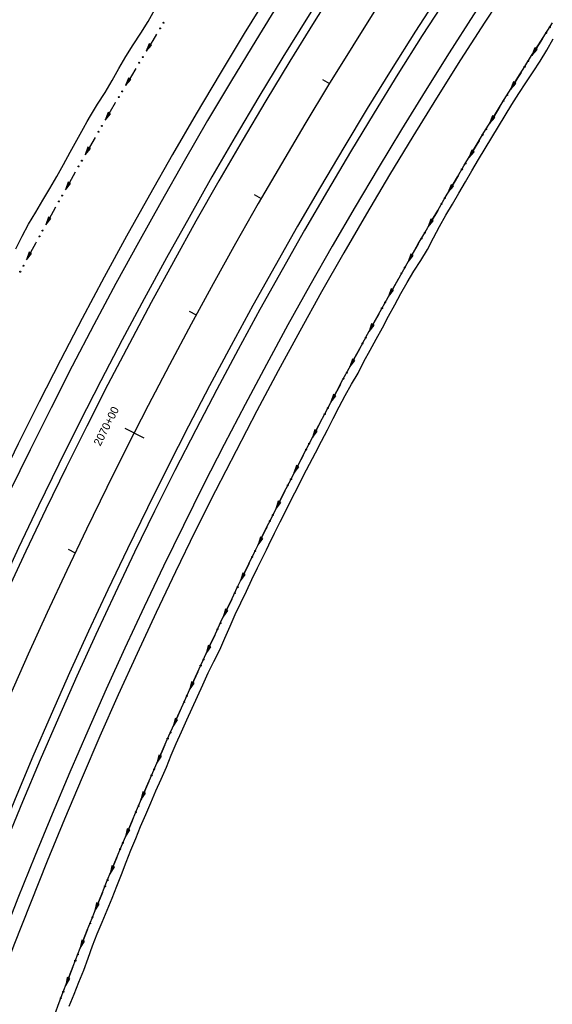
# Model space of a CAD drawing. Extents: x 1611108 to 1749517, y 619561 to 797725.
# Drawn here: x 1713935 to 1714335, y 763528 to 764266 of the extents above; entities that cross this region are included whole.
import ezdxf

# ---------------------------------------------------------------- set-up
doc = ezdxf.new("R2010")
doc.units = 0
for name, color, linetype in [('R_Ditch', 7, 'Continuous'), ('R_Horz Alg', 7, 'Continuous'), ('R_Horz Alg Stationing', 7, 'Continuous'), ('R_Proposed Const Limits', 7, 'Continuous'), ('R_Proposed Road', 7, 'Continuous')]:
    doc.layers.add(name, color=color, linetype=linetype)

msp = doc.modelspace()

# ---------------------------------------------------------------- linework, layer by layer
at = {"layer": 'R_Ditch'}
for p, q in [((1714032.43, 764248.1), (1714030.22, 764242.42)), ((1714032.43, 764248.1), (1714030.22, 764242.42)), ((1714030.22, 764242.42), (1714034.24, 764247)), ((1714030.22, 764242.42), (1714034.24, 764247)), ((1714034.24, 764247), (1714032.43, 764248.1)), ((1714034.24, 764247), (1714032.43, 764248.1)), ((1714321.47, 764244.96), (1714319.15, 764239.33)), ((1714319.15, 764239.33), (1714323.25, 764243.83)), ((1714323.25, 764243.83), (1714321.47, 764244.96)), ((1714016.92, 764222.37), (1714014.76, 764216.67)), ((1714016.92, 764222.37), (1714014.76, 764216.67)), ((1714018.74, 764221.28), (1714016.92, 764222.37)), ((1714018.74, 764221.28), (1714016.92, 764222.37)), ((1714014.76, 764216.67), (1714018.74, 764221.28)), ((1714014.76, 764216.67), (1714018.74, 764221.28)), ((1714305.5, 764219.51), (1714303.23, 764213.86)), ((1714303.23, 764213.86), (1714307.3, 764218.39)), ((1714307.3, 764218.39), (1714305.5, 764219.51)), ((1714001.62, 764196.51), (1713999.51, 764190.79)), ((1714001.62, 764196.51), (1713999.51, 764190.79)), ((1713999.51, 764190.79), (1714003.45, 764195.44)), ((1713999.51, 764190.79), (1714003.45, 764195.44)), ((1714003.45, 764195.44), (1714001.62, 764196.51)), ((1714003.45, 764195.44), (1714001.62, 764196.51)), ((1714289.73, 764193.94), (1714287.5, 764188.27)), ((1714287.5, 764188.27), (1714291.53, 764192.84)), ((1714291.53, 764192.84), (1714289.73, 764193.94)), ((1713986.53, 764170.52), (1713984.47, 764164.79)), ((1713986.53, 764170.52), (1713984.47, 764164.79)), ((1713988.37, 764169.47), (1713986.53, 764170.52)), ((1713988.37, 764169.47), (1713986.53, 764170.52)), ((1713984.47, 764164.79), (1713988.37, 764169.47)), ((1713984.47, 764164.79), (1713988.37, 764169.47)), ((1714274.15, 764168.25), (1714271.96, 764162.56)), ((1714271.96, 764162.56), (1714275.96, 764167.16)), ((1714275.96, 764167.16), (1714274.15, 764168.25)), ((1713971.66, 764144.42), (1713969.64, 764138.67)), ((1713971.66, 764144.42), (1713969.64, 764138.67)), ((1713969.64, 764138.67), (1713973.5, 764143.38)), ((1713969.64, 764138.67), (1713973.5, 764143.38)), ((1713973.5, 764143.38), (1713971.66, 764144.42)), ((1713973.5, 764143.38), (1713971.66, 764144.42)), ((1714258.75, 764142.44), (1714256.62, 764136.74)), ((1714256.62, 764136.74), (1714260.58, 764141.37)), ((1714260.58, 764141.37), (1714258.75, 764142.44)), ((1713956.99, 764118.19), (1713955.02, 764112.43)), ((1713956.99, 764118.19), (1713955.02, 764112.43)), ((1713958.84, 764117.17), (1713956.99, 764118.19)), ((1713958.84, 764117.17), (1713956.99, 764118.19)), ((1713955.02, 764112.43), (1713958.84, 764117.17)), ((1713955.02, 764112.43), (1713958.84, 764117.17)), ((1714243.56, 764116.52), (1714241.47, 764110.8)), ((1714241.47, 764110.8), (1714245.4, 764115.46)), ((1714245.4, 764115.46), (1714243.56, 764116.52)), ((1713942.54, 764091.85), (1713940.61, 764086.07)), ((1713942.54, 764091.85), (1713940.61, 764086.07)), ((1713940.61, 764086.07), (1713944.4, 764090.85)), ((1713940.61, 764086.07), (1713944.4, 764090.85)), ((1713944.4, 764090.85), (1713942.54, 764091.85)), ((1713944.4, 764090.85), (1713942.54, 764091.85)), ((1714228.57, 764090.48), (1714226.52, 764084.74)), ((1714226.52, 764084.74), (1714230.41, 764089.44)), ((1714230.41, 764089.44), (1714228.57, 764090.48)), ((1714213.77, 764064.33), (1714211.77, 764058.58)), ((1714211.77, 764058.58), (1714215.62, 764063.3)), ((1714215.62, 764063.3), (1714213.77, 764064.33)), ((1714199.17, 764038.07), (1714197.21, 764032.31)), ((1714197.21, 764032.31), (1714201.03, 764037.05)), ((1714201.03, 764037.05), (1714199.17, 764038.07)), ((1714184.77, 764011.7), (1714182.85, 764005.92)), ((1714182.85, 764005.92), (1714186.63, 764010.7)), ((1714186.63, 764010.7), (1714184.77, 764011.7)), ((1714170.57, 763985.23), (1714168.69, 763979.43)), ((1714168.69, 763979.43), (1714172.44, 763984.23)), ((1714172.44, 763984.23), (1714170.57, 763985.23)), ((1714156.57, 763958.64), (1714154.73, 763952.84)), ((1714154.73, 763952.84), (1714158.44, 763957.67)), ((1714158.44, 763957.67), (1714156.57, 763958.64)), ((1714142.76, 763931.96), (1714140.97, 763926.13)), ((1714140.97, 763926.13), (1714144.65, 763930.99)), ((1714144.65, 763930.99), (1714142.76, 763931.96)), ((1714129.16, 763905.17), (1714127.41, 763899.33)), ((1714127.41, 763899.33), (1714131.05, 763904.21)), ((1714131.05, 763904.21), (1714129.16, 763905.17)), ((1714115.76, 763878.27), (1714114.06, 763872.42)), ((1714114.06, 763872.42), (1714117.66, 763877.34)), ((1714117.66, 763877.34), (1714115.76, 763878.27)), ((1714102.57, 763851.28), (1714100.91, 763845.41)), ((1714100.91, 763845.41), (1714104.47, 763850.36)), ((1714104.47, 763850.36), (1714102.57, 763851.28)), ((1714089.58, 763824.19), (1714087.97, 763818.31)), ((1714087.97, 763818.31), (1714091.49, 763823.28)), ((1714091.49, 763823.28), (1714089.58, 763824.19)), ((1714076.79, 763797), (1714075.22, 763791.11)), ((1714075.22, 763791.11), (1714078.71, 763796.1)), ((1714078.71, 763796.1), (1714076.79, 763797)), ((1714064.21, 763769.71), (1714062.69, 763763.81)), ((1714062.69, 763763.81), (1714066.14, 763768.83)), ((1714066.14, 763768.83), (1714064.21, 763769.71)), ((1714051.84, 763742.33), (1714050.36, 763736.42)), ((1714053.77, 763741.47), (1714051.84, 763742.33)), ((1714050.36, 763736.42), (1714053.77, 763741.47)), ((1714039.67, 763714.86), (1714038.23, 763708.94)), ((1714038.23, 763708.94), (1714041.61, 763714.01)), ((1714041.61, 763714.01), (1714039.67, 763714.86)), ((1714027.71, 763687.3), (1714026.32, 763681.36)), ((1714026.32, 763681.36), (1714029.66, 763686.46)), ((1714029.66, 763686.46), (1714027.71, 763687.3)), ((1714015.96, 763659.64), (1714014.61, 763653.7)), ((1714014.61, 763653.7), (1714017.91, 763658.82)), ((1714017.91, 763658.82), (1714015.96, 763659.64)), ((1714004.42, 763631.9), (1714003.11, 763625.95)), ((1714003.11, 763625.95), (1714006.38, 763631.1)), ((1714006.38, 763631.1), (1714004.42, 763631.9)), ((1713993.08, 763604.08), (1713991.83, 763598.11)), ((1713991.83, 763598.11), (1713995.04, 763603.29)), ((1713995.04, 763603.29), (1713993.08, 763604.08)), ((1713981.96, 763576.16), (1713980.75, 763570.19)), ((1713980.75, 763570.19), (1713983.93, 763575.39)), ((1713983.93, 763575.39), (1713981.96, 763576.16)), ((1713971.05, 763548.17), (1713969.89, 763542.19)), ((1713969.89, 763542.19), (1713973.02, 763547.41)), ((1713973.02, 763547.41), (1713971.05, 763548.17))]:
    msp.add_line(p, q, dxfattribs=at)
for points in [[(1713961.65, 763520.54), (1713965.07, 763529.59), (1713968.53, 763538.64), (1713972, 763547.68), (1713975.49, 763556.71), (1713979, 763565.74), (1713982.54, 763574.75), (1713986.1, 763583.76), (1713989.68, 763592.75), (1713993.28, 763601.74), (1713996.91, 763610.72), (1714000.55, 763619.69), (1714004.22, 763628.65), (1714007.91, 763637.6), (1714011.62, 763646.55), (1714015.36, 763655.48), (1714019.11, 763664.41), (1714022.89, 763673.32), (1714026.69, 763682.23), (1714030.51, 763691.13), (1714034.35, 763700.02), (1714038.22, 763708.89), (1714042.1, 763717.76), (1714046.01, 763726.62), (1714049.94, 763735.47), (1714053.88, 763744.32), (1714057.86, 763753.15), (1714061.85, 763761.97), (1714065.86, 763770.78), (1714069.9, 763779.58), (1714073.96, 763788.37), (1714078.03, 763797.16), (1714082.13, 763805.93), (1714086.26, 763814.69), (1714090.4, 763823.45), (1714094.56, 763832.19), (1714098.75, 763840.92), (1714102.95, 763849.64), (1714107.18, 763858.36), (1714111.43, 763867.06), (1714113.87, 763872.03), (1714115.7, 763875.75), (1714119.99, 763884.43), (1714124.3, 763893.1), (1714128.64, 763901.77), (1714132.99, 763910.42), (1714137.37, 763919.06), (1714141.76, 763927.69), (1714146.18, 763936.3), (1714150.62, 763944.91), (1714155.08, 763953.51), (1714159.56, 763962.1), (1714160.41, 763963.72), (1714164.06, 763970.67), (1714168.58, 763979.24), (1714173.13, 763987.79), (1714177.69, 763996.34), (1714182.28, 764004.87), (1714186.89, 764013.39), (1714191.51, 764021.9), (1714196.16, 764030.4), (1714200.83, 764038.89), (1714205.52, 764047.37), (1714210.23, 764055.83), (1714214.96, 764064.29), (1714219.71, 764072.73), (1714224.48, 764081.16), (1714229.28, 764089.58), (1714234.09, 764097.99), (1714238.92, 764106.39), (1714243.78, 764114.77), (1714248.65, 764123.15), (1714253.55, 764131.51), (1714258.46, 764139.86), (1714263.4, 764148.2), (1714268.35, 764156.53), (1714273.33, 764164.84), (1714278.33, 764173.15), (1714283.35, 764181.44), (1714288.39, 764189.72), (1714293.44, 764197.99), (1714298.52, 764206.24), (1714303.62, 764214.49), (1714308.74, 764222.72), (1714313.88, 764230.94), (1714319.04, 764239.14), (1714324.22, 764247.34), (1714329.42, 764255.52), (1714334.64, 764263.69)], [(1714038.02, 764255.24), (1714035.18, 764250.58), (1714030.22, 764242.42)], [(1714038.02, 764255.24), (1714035.18, 764250.58), (1714030.22, 764242.42)], [(1714038.04, 764255.27), (1714038.02, 764255.24)], [(1714038.04, 764255.27), (1714038.02, 764255.24)], [(1714327.18, 764252), (1714324.22, 764247.34), (1714319.15, 764239.33)], [(1714327.2, 764252.03), (1714327.18, 764252)], [(1714022.46, 764229.55), (1714019.14, 764224.02), (1714014.76, 764216.67)], [(1714022.46, 764229.55), (1714019.14, 764224.02), (1714014.76, 764216.67)], [(1714022.48, 764229.58), (1714022.46, 764229.55)], [(1714022.48, 764229.58), (1714022.46, 764229.55)], [(1714311.16, 764226.59), (1714308.74, 764222.72), (1714303.62, 764214.49), (1714303.23, 764213.86)], [(1714311.18, 764226.62), (1714311.16, 764226.59)], [(1714007.1, 764203.73), (1714003.33, 764197.33), (1713999.51, 764190.79)], [(1714007.1, 764203.73), (1714003.33, 764197.33), (1713999.51, 764190.79)], [(1714007.12, 764203.76), (1714007.1, 764203.73)], [(1714007.12, 764203.76), (1714007.1, 764203.73)], [(1714295.33, 764201.06), (1714293.44, 764197.99), (1714288.39, 764189.72), (1714287.5, 764188.27)], [(1714295.35, 764201.09), (1714295.33, 764201.06)], [(1713991.95, 764177.79), (1713987.74, 764170.5), (1713984.47, 764164.79)], [(1713991.95, 764177.79), (1713987.74, 764170.5), (1713984.47, 764164.79)], [(1713991.97, 764177.82), (1713991.95, 764177.79)], [(1713991.97, 764177.82), (1713991.95, 764177.79)], [(1714279.7, 764175.41), (1714278.33, 764173.15), (1714273.33, 764164.84), (1714271.96, 764162.56)], [(1714279.72, 764175.44), (1714279.7, 764175.41)], [(1713977.01, 764151.73), (1713972.38, 764143.54), (1713969.64, 764138.67)], [(1713977.01, 764151.73), (1713972.38, 764143.54), (1713969.64, 764138.67)], [(1713977.03, 764151.76), (1713977.01, 764151.73)], [(1713977.03, 764151.76), (1713977.01, 764151.73)], [(1714264.26, 764149.65), (1714263.4, 764148.2), (1714258.46, 764139.86), (1714256.62, 764136.74)], [(1714264.28, 764149.68), (1714264.26, 764149.65)], [(1713962.29, 764125.55), (1713962.26, 764125.5), (1713957.24, 764116.46), (1713955.02, 764112.43)], [(1713962.29, 764125.55), (1713962.26, 764125.5), (1713957.24, 764116.46), (1713955.02, 764112.43)], [(1713962.31, 764125.58), (1713962.29, 764125.55)], [(1713962.31, 764125.58), (1713962.29, 764125.55)], [(1714249.01, 764123.77), (1714248.65, 764123.15), (1714243.78, 764114.77), (1714241.47, 764110.8)], [(1714249.03, 764123.8), (1714249.01, 764123.77)], [(1713947.78, 764099.25), (1713947.27, 764098.33), (1713942.33, 764089.24), (1713940.61, 764086.07)], [(1713947.78, 764099.25), (1713947.27, 764098.33), (1713942.33, 764089.24), (1713940.61, 764086.07)], [(1713947.8, 764099.28), (1713947.78, 764099.25)], [(1713947.8, 764099.28), (1713947.78, 764099.25)], [(1714233.96, 764097.77), (1714229.28, 764089.58), (1714226.52, 764084.74)], [(1714233.98, 764097.8), (1714233.96, 764097.77)], [(1714219.11, 764071.66), (1714214.96, 764064.29), (1714211.77, 764058.58)], [(1714219.13, 764071.69), (1714219.11, 764071.66)], [(1714204.45, 764045.44), (1714200.83, 764038.89), (1714197.21, 764032.31)], [(1714204.47, 764045.47), (1714204.45, 764045.44)], [(1714190, 764019.11), (1714186.89, 764013.39), (1714182.85, 764005.92)], [(1714190.01, 764019.14), (1714190, 764019.11)], [(1714175.74, 763992.67), (1714173.13, 763987.79), (1714168.69, 763979.43)], [(1714175.75, 763992.71), (1714175.74, 763992.67)], [(1714161.68, 763966.13), (1714160.41, 763963.72), (1714159.56, 763962.1), (1714155.08, 763953.51), (1714154.73, 763952.83)], [(1714161.69, 763966.16), (1714161.68, 763966.13)], [(1714147.82, 763939.48), (1714146.18, 763936.3), (1714141.76, 763927.69), (1714140.97, 763926.13)], [(1714147.84, 763939.51), (1714147.82, 763939.48)], [(1714134.16, 763912.73), (1714132.99, 763910.42), (1714128.64, 763901.77), (1714127.42, 763899.33)], [(1714134.18, 763912.76), (1714134.16, 763912.73)], [(1714120.7, 763885.87), (1714119.99, 763884.43), (1714115.7, 763875.75), (1714114.06, 763872.42)], [(1714120.72, 763885.9), (1714120.7, 763885.87)], [(1714107.45, 763858.91), (1714107.18, 763858.36), (1714102.95, 763849.64), (1714100.91, 763845.41)], [(1714107.47, 763858.95), (1714107.45, 763858.91)], [(1714094.4, 763831.86), (1714090.4, 763823.45), (1714087.97, 763818.31)], [(1714094.42, 763831.89), (1714094.4, 763831.86)], [(1714081.56, 763804.7), (1714078.03, 763797.16), (1714075.22, 763791.11)], [(1714081.58, 763804.74), (1714081.56, 763804.7)], [(1714068.92, 763777.45), (1714065.86, 763770.78), (1714062.69, 763763.81)], [(1714068.94, 763777.49), (1714068.92, 763777.45)], [(1714056.49, 763750.11), (1714053.88, 763744.32), (1714050.36, 763736.42)], [(1714056.51, 763750.14), (1714056.49, 763750.11)], [(1714044.26, 763722.67), (1714042.1, 763717.76), (1714038.23, 763708.94)], [(1714044.28, 763722.71), (1714044.27, 763722.67)], [(1714032.25, 763695.14), (1714030.51, 763691.13), (1714026.69, 763682.23), (1714026.32, 763681.36)], [(1714032.26, 763695.18), (1714032.25, 763695.14)], [(1714020.44, 763667.53), (1714019.11, 763664.41), (1714015.36, 763655.48), (1714014.61, 763653.7)], [(1714020.45, 763667.56), (1714020.44, 763667.53)], [(1714008.83, 763639.82), (1714007.91, 763637.6), (1714004.22, 763628.65), (1714003.12, 763625.95)], [(1714008.85, 763639.85), (1714008.83, 763639.82)], [(1713997.44, 763612.03), (1713996.91, 763610.72), (1713993.28, 763601.74), (1713991.83, 763598.11)], [(1713997.45, 763612.06), (1713997.44, 763612.03)], [(1713986.26, 763584.15), (1713986.1, 763583.76), (1713982.54, 763574.75), (1713980.75, 763570.19)], [(1713986.27, 763584.18), (1713986.26, 763584.15)], [(1713975.28, 763556.18), (1713972, 763547.68), (1713969.89, 763542.19)], [(1713975.3, 763556.22), (1713975.28, 763556.18)], [(1713964.54, 763528.18), (1713964.52, 763528.14)]]:
    msp.add_lwpolyline(points, dxfattribs=at)
for centre in [(1714040.67, 764259.5), (1714040.67, 764259.5), (1714043.3, 764263.77), (1714043.3, 764263.77), (1714332.61, 764260.44), (1714329.91, 764256.22), (1714027.66, 764238.12), (1714027.66, 764238.12), (1714025.07, 764233.83), (1714025.07, 764233.83), (1714313.85, 764230.83), (1714316.52, 764235.07), (1714009.68, 764208.04), (1714009.68, 764208.04), (1714012.24, 764212.35), (1714012.24, 764212.35), (1714300.63, 764209.58), (1714298, 764205.32), (1713997.02, 764186.45), (1713997.02, 764186.45), (1713994.5, 764182.12), (1713994.5, 764182.12), (1714282.33, 764179.69), (1714284.93, 764183.97), (1713979.53, 764156.08), (1713979.53, 764156.08), (1713982.01, 764160.43), (1713982.01, 764160.43), (1714269.42, 764158.25), (1714266.86, 764153.94), (1713967.21, 764134.29), (1713967.21, 764134.29), (1713964.77, 764129.92), (1713964.77, 764129.92), (1714251.58, 764128.08), (1714254.11, 764132.4), (1713950.22, 764103.64), (1713950.22, 764103.64), (1713952.63, 764108.03), (1713952.63, 764108.03), (1714239, 764106.45), (1714236.5, 764102.1), (1713938.26, 764081.65), (1713938.26, 764081.65), (1713935.89, 764077.24), (1713935.89, 764077.24), (1714221.61, 764076.02), (1714224.08, 764080.38), (1714209.36, 764054.19), (1714206.92, 764049.81), (1714192.43, 764023.5), (1714194.83, 764027.9), (1714180.51, 764001.5), (1714178.14, 763997.08), (1714164.04, 763970.56), (1714166.38, 763974.99), (1714152.46, 763948.37), (1714150.15, 763943.93), (1714138.73, 763921.66), (1714136.46, 763917.19), (1714122.97, 763890.35), (1714125.21, 763894.83), (1714111.89, 763867.91), (1714109.69, 763863.41), (1714098.77, 763840.89), (1714096.61, 763836.37), (1714083.73, 763809.23), (1714085.86, 763813.77), (1714073.15, 763786.55), (1714071.05, 763782), (1714060.65, 763759.24), (1714058.59, 763754.67), (1714046.33, 763727.25), (1714048.36, 763731.83), (1714034.27, 763699.74), (1714036.27, 763704.33), (1714024.39, 763676.74), (1714022.43, 763672.14), (1714012.72, 763649.07), (1714010.79, 763644.44), (1713999.36, 763616.66), (1714001.25, 763621.3), (1713988.15, 763588.8), (1713990, 763593.45), (1713978.96, 763565.52), (1713977.14, 763560.85), (1713968.13, 763537.5), (1713966.34, 763532.82)]:
    msp.add_circle(centre, 0.375, dxfattribs=at)
at = {"layer": 'R_Horz Alg'}
msp.add_arc((1717426.61, 762226.09), 3819.72, 112.5, 179.5, dxfattribs=at)
at = {"layer": 'R_Horz Alg Stationing'}
for points in [[(1714162.37, 764221.31), (1714167.49, 764218.18)], [(1714111.26, 764135.18), (1714116.46, 764132.19)], [(1714062.42, 764047.74), (1714067.7, 764044.88)], [(1714014.11, 763959.96), (1714028.37, 763952.71)], [(1713971.69, 763869.18), (1713977.11, 763866.6)]]:
    msp.add_lwpolyline(points, dxfattribs=at)
at = {"layer": 'R_Proposed Const Limits'}
for points in [[(1713932.56, 764094.46), (1713937.21, 764103.74), (1713942.13, 764112.87), (1713947.42, 764121.81), (1713952.74, 764130.72), (1713958.01, 764139.66), (1713963.2, 764148.64), (1713968.26, 764157.69), (1713973.25, 764166.78), (1713978.27, 764175.85), (1713983.32, 764184.92), (1713986.02, 764189.74), (1713988.39, 764193.96), (1713993.77, 764202.83), (1713999.39, 764211.56), (1714004.75, 764220.44), (1714009.78, 764229.51), (1714015.03, 764238.45), (1714020.57, 764247.22), (1714026.14, 764255.97), (1714031.69, 764264.73), (1714036.8, 764273.76)], [(1713972.56, 763526.78), (1713976.17, 763535.74), (1713979.81, 763544.69), (1713983.47, 763553.64), (1713986.79, 763562.71), (1713989.91, 763571.86), (1713993.47, 763580.85), (1713997.18, 763589.77), (1714000.92, 763598.68), (1714004.64, 763607.6), (1714008.22, 763616.57), (1714011.81, 763625.54), (1714015.28, 763634.56), (1714018.75, 763643.58), (1714022.41, 763652.53), (1714026.05, 763661.48), (1714029.86, 763670.36), (1714033.69, 763679.23), (1714037.54, 763688.09), (1714041.41, 763696.95), (1714045.35, 763705.77), (1714048.89, 763714.77), (1714052.64, 763723.68), (1714056.67, 763732.46), (1714060.65, 763741.27), (1714064.7, 763750.04), (1714068.76, 763758.81), (1714072.78, 763767.6), (1714076.59, 763776.48), (1714080.97, 763785.1), (1714085.34, 763793.73), (1714089.15, 763802.61), (1714093.06, 763811.46), (1714097, 763820.29), (1714101.13, 763829.02), (1714105.28, 763837.75), (1714109.45, 763846.47), (1714113.64, 763855.18), (1714117.85, 763863.88), (1714120.27, 763868.84), (1714122.09, 763872.57), (1714126.38, 763881.23), (1714130.7, 763889.87), (1714135.05, 763898.51), (1714139.41, 763907.13), (1714143.79, 763915.75), (1714148.2, 763924.35), (1714152.62, 763932.95), (1714157, 763941.57), (1714161.55, 763950.09), (1714166, 763958.68), (1714166.84, 763960.3), (1714170.46, 763967.25), (1714174.94, 763975.82), (1714179.45, 763984.37), (1714184.02, 763992.89), (1714188.96, 764001.2), (1714193.4, 764009.8), (1714198.03, 764018.29), (1714202.68, 764026.76), (1714207.26, 764035.27), (1714211.81, 764043.81), (1714216.44, 764052.3), (1714221.09, 764060.77), (1714225.77, 764069.24), (1714230.8, 764077.5), (1714236.03, 764085.64), (1714241.07, 764093.9), (1714245.51, 764102.51), (1714250, 764111.08), (1714254.7, 764119.54), (1714259.71, 764127.81), (1714264.52, 764136.2), (1714269.39, 764144.56), (1714274.3, 764152.9), (1714279.22, 764161.22), (1714284.17, 764169.54), (1714289.15, 764177.83), (1714294.16, 764186.11), (1714299.18, 764194.38), (1714304.26, 764202.61), (1714309.45, 764210.78), (1714314.79, 764218.84), (1714320.15, 764226.9), (1714325.48, 764234.97), (1714330.46, 764243.28), (1714335.3, 764251.67)]]:
    msp.add_lwpolyline(points, dxfattribs=at)
at = {"layer": 'R_Proposed Road'}
for radius in [3893.72, 3883.72, 3859.72, 3853.72, 3785.72, 3779.72, 3755.72, 3745.72]:
    msp.add_arc((1717426.61, 762226.09), radius, 112.5, 179.5, dxfattribs=at)

# ---------------------------------------------------------------- texts
at = {"layer": 'R_Horz Alg Stationing'}
msp.add_text('2070+00', height=6, rotation=63.06525, dxfattribs=at).set_placement((1713995.84, 763946.08))

doc.saveas('drawing.dxf')
